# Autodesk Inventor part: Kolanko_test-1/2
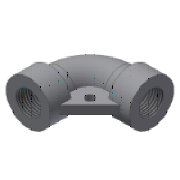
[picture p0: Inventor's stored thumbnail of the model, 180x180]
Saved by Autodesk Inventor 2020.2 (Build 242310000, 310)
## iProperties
Manager: www.cadconsulting.pl
Company: Fabian Stasiak CAD Consulting
IsCustomPart: 0
Created: 2014-08
Part Number: Kolanko_test-1/2
Material: Ogólny
Document SubType Name: Modeling
Designer: F.Stasiak
Language: pl-PL
Size Designation: 1/2
Categories: <MemberInstance><Categories><Category DisplayName="Rury cienko- i grubościenne" InternalName="4347fa0f-2144-441d-94cd-e3e15c92b736" Mnemonic="TUBEANDPIPE"><Cate
Density: 1 g/cm^3
Appearance: Domyślna
Catalog Web Link: www.expertbooks.pl
Author: F.Stasiak
Subject: Zbiór ćwiczeń. Autodesk Inventor 2020. Kurs Professional
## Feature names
1. Przeciągnięcie1
2. Wyciągnięcie proste1 [Extrusion]
3. Wyciągnięcie proste2 [Extrusion]
4. Wyciągnięcie proste5 [Extrusion]
## Parameters: d0 = 45.7835 mm, d1 = 45.7835 mm, d2 = 22.89175 mm, d4 = 0, d5 = 0, d6 = 33.02 mm, d7 = 18.3134 mm, d9 = 15.748 mm, d10 = 0, d11 = 33.02 mm, d12 = 15.748 mm, d13 = 0, d19 = 19.8628 mm, d20 = 0, d21 = 19.8628 mm, d22 = 0, ID = 18.3134 mm, OD = 33.02 mm, GL = 15.748 mm, G = 3.175 mm, d23 = 3.175 mm, d24 = 6.35 mm, d26 = 6.35 mm, d27 = 0
